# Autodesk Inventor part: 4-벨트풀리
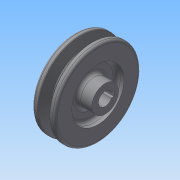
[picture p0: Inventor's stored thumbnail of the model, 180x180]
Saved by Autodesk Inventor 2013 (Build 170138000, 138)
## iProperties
Created: 2015-02
Part Number: 4-벨트풀리
Material: 일반
Document SubType Name: Modeling
Designer: Administrator
Density: 1 g/cm^3
Author: Administrator
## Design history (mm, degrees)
sketch "스케치1"
  geometry: L1 (0, 0)-(25, 0); L2 (0, 0)-(0, 11); L3 (0, 11)-(6, 11); L4 (6, 11)-(6, 21.5); L5 (6, 21.5)-(0, 21.5); L6 (0, 21.5)-(0, 35.2); L7 (0, 35.2)-(4.675, 35.2); L8 (4.675, 35.2)-(7.426, 26.2); L9 (7.426, 26.2)-(11.574, 26.2); L10 (11.574, 26.2)-(14.325, 35.2); L11 (14.325, 35.2)-(19, 35.2); L12 (19, 35.2)-(19, 21.5); L13 (19, 21.5)-(13, 21.5); L14 (13, 21.5)-(13, 11); L15 (13, 11)-(25, 11); L16 (25, 11)-(25, 0); 2 further points
  constraints: 32 end point, 8 parallel, 5 collinear, 3 equal length, 3 perpendicular, 2 point on line, 2 vertical alignment, 1 horizontal, 1 horizontal alignment
  dimensions: "d0" = 65 diameter of point (5.5, 32.5) L1; "d2" = 2.7 distance from line of point (5.5, 32.5) L7; "d3" = 6.3 vertical distance of L8.end point (5.5, 32.5); "d4" = 8 distance of point (13.5, 32.5) point (5.5, 32.5); "d5" = 34 deg angle of L10 L8; "d6" = 19 distance between parallel lines of L12 L6; "d7" = 6 distance from line of L5.end L4; "d8" = 43 diameter of L5 L1; "d9" = 22 diameter of L15 L1; "d11" = 25 distance of L1.start L1.end
revolve "회전1" sketch "스케치1" stored, may be unused: angle "d12" = 90 deg
sketch "스케치2"
  geometry: L1 (-2, 5.123)-(-2, 7.3); L2 (-2, 7.3)-(2, 7.3); L3 (2, 7.3)-(2, 5.123); C1 r 11 at (0, 0) reference; A1 r 5.5 centre (0, 0) between (-2, 5.123) and (2, 5.123)
  constraints: 6 end point, 2 parallel, 2 point on circle, 1 centre point, 1 coincident, 1 perpendicular, 1 vertical
  dimensions: "d13" = 11 diameter of A1; "d15" = 12.8 dimension on A1 L2; "d16" = 4 distance of L1.end L2.end
extrude "돌출1" cut sketch "스케치2" stored distance "d17" = 10; taper "d18" = 0 deg
fillet "모깎기1" dims "d19" = 1, "d20" = 0.5, "d21" = 2, "d22" = 3
node "솔리드1"
